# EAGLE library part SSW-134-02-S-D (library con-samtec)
THROUGH-HOLE .025" SQ POST SOCKET Source: Samtec SSW.pdf
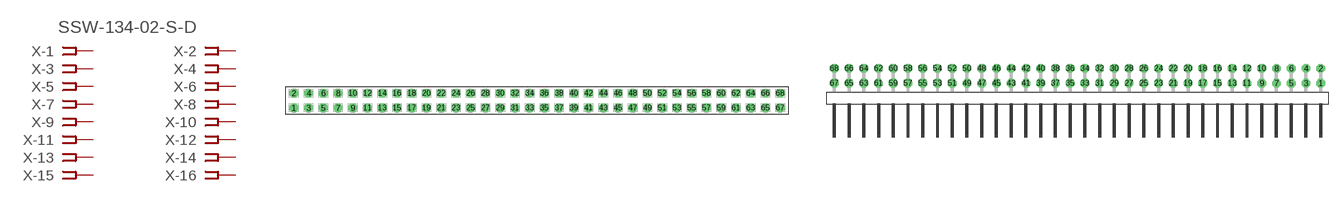
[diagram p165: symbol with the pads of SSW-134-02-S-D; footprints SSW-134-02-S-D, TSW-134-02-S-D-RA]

Designator prefix X; gates -1=FPINV -2=FPIN -3=FPIN -4=FPIN -5=FPIN -6=FPIN -7=FPIN -8=FPIN -9=FPIN -10=FPIN -11=FPIN -12=FPIN -13=FPIN -14=FPIN -15=FPIN -16=FPIN -17=FPIN -18=FPIN -19=FPIN -20=FPIN -21=FPIN -22=FPIN -23=FPIN -24=FPIN -25=FPIN -26=FPIN -27=FPIN -28=FPIN -29=FPIN -30=FPIN -31=FPIN -32=FPIN -33=FPIN -34=FPIN -35=FPIN -36=FPIN -37=FPIN -38=FPIN -39=FPIN -40=FPIN -41=FPIN -42=FPIN -43=FPIN -44=FPIN -45=FPIN -46=FPIN -47=FPIN -48=FPIN -49=FPIN -50=FPIN -51=FPIN -52=FPIN -53=FPIN -54=FPIN -55=FPIN -56=FPIN -57=FPIN -58=FPIN -59=FPIN -60=FPIN -61=FPIN -62=FPIN -63=FPIN -64=FPIN -65=FPIN -66=FPIN -67=FPIN -68=FPIN

## SSW-134-02-S-D (MPN: SSW-134-02-S-D; OC_FARNELL: unknown; OC_NEWARK: 11P9869)  [SSW-134-02-S-D]
1  -1:1  pas
2  -2:1  pas
3  -3:1  pas
4  -4:1  pas
5  -5:1  pas
6  -6:1  pas
7  -7:1  pas
8  -8:1  pas
9  -9:1  pas
10  -10:1  pas
11  -11:1  pas
12  -12:1  pas
13  -13:1  pas
14  -14:1  pas
15  -15:1  pas
16  -16:1  pas
17  -17:1  pas
18  -18:1  pas
19  -19:1  pas
20  -20:1  pas
21  -21:1  pas
22  -22:1  pas
23  -23:1  pas
24  -24:1  pas
25  -25:1  pas
26  -26:1  pas
27  -27:1  pas
28  -28:1  pas
29  -29:1  pas
30  -30:1  pas
31  -31:1  pas
32  -32:1  pas
33  -33:1  pas
34  -34:1  pas
35  -35:1  pas
36  -36:1  pas
37  -37:1  pas
38  -38:1  pas
39  -39:1  pas
40  -40:1  pas
41  -41:1  pas
42  -42:1  pas
43  -43:1  pas
44  -44:1  pas
45  -45:1  pas
46  -46:1  pas
47  -47:1  pas
48  -48:1  pas
49  -49:1  pas
50  -50:1  pas
51  -51:1  pas
52  -52:1  pas
53  -53:1  pas
54  -54:1  pas
55  -55:1  pas
56  -56:1  pas
57  -57:1  pas
58  -58:1  pas
59  -59:1  pas
60  -60:1  pas
61  -61:1  pas
62  -62:1  pas
63  -63:1  pas
64  -64:1  pas
65  -65:1  pas
66  -66:1  pas
67  -67:1  pas
68  -68:1  pas

## SSW-134-02-S-D-RA (MPN: SSW-134-02-S-D-RA; OC_FARNELL: unknown; OC_NEWARK: 11P9870)  [TSW-134-02-S-D-RA]
Pads as for SSW-134-02-S-D

## Footprint SSW-134-02-S-D (pad centres in mm)
THROUGH-HOLE .025" SQ POST SOCKET Source: Samtec SSW.pdf
drill 1 pad 1.5 octagon: 1 -41.91,-1.27; 2 -41.91,1.27; 3 -39.37,-1.27; 4 -39.37,1.27; 5 -36.83,-1.27; 6 -36.83,1.27; 7 -34.29,-1.27; 8 -34.29,1.27; 9 -31.75,-1.27; 10 -31.75,1.27; 11 -29.21,-1.27; 12 -29.21,1.27; 13 -26.67,-1.27; 14 -26.67,1.27; 15 -24.13,-1.27; 16 -24.13,1.27; 17 -21.59,-1.27; 18 -21.59,1.27; 19 -19.05,-1.27; 20 -19.05,1.27; 21 -16.51,-1.27; 22 -16.51,1.27; 23 -13.97,-1.27; 24 -13.97,1.27; 25 -11.43,-1.27; 26 -11.43,1.27; 27 -8.89,-1.27; 28 -8.89,1.27; 29 -6.35,-1.27; 30 -6.35,1.27; 31 -3.81,-1.27; 32 -3.81,1.27; 33 -1.27,-1.27; 34 -1.27,1.27; 35 1.27,-1.27; 36 1.27,1.27; 37 3.81,-1.27; 38 3.81,1.27; 39 6.35,-1.27; 40 6.35,1.27; 41 8.89,-1.27; 42 8.89,1.27; 43 11.43,-1.27; 44 11.43,1.27; 45 13.97,-1.27; 46 13.97,1.27; 47 16.51,-1.27; 48 16.51,1.27; 49 19.05,-1.27; 50 19.05,1.27; 51 21.59,-1.27; 52 21.59,1.27; 53 24.13,-1.27; 54 24.13,1.27; 55 26.67,-1.27; 56 26.67,1.27; 57 29.21,-1.27; 58 29.21,1.27; 59 31.75,-1.27; 60 31.75,1.27; 61 34.29,-1.27; 62 34.29,1.27; 63 36.83,-1.27; 64 36.83,1.27; 65 39.37,-1.27; 66 39.37,1.27; 67 41.91,-1.27; 68 41.91,1.27

## Footprint TSW-134-02-S-D-RA (pad centres in mm)
THROUGH-HOLE .025" SQ POST HEADER Source: Samtec TSW.pdf
drill 1 pad 1.5 octagon: 1 41.91,1.524; 2 41.91,4.064; 3 39.37,1.524; 4 39.37,4.064; 5 36.83,1.524; 6 36.83,4.064; 7 34.29,1.524; 8 34.29,4.064; 9 31.75,1.524; 10 31.75,4.064; 11 29.21,1.524; 12 29.21,4.064; 13 26.67,1.524; 14 26.67,4.064; 15 24.13,1.524; 16 24.13,4.064; 17 21.59,1.524; 18 21.59,4.064; 19 19.05,1.524; 20 19.05,4.064; 21 16.51,1.524; 22 16.51,4.064; 23 13.97,1.524; 24 13.97,4.064; 25 11.43,1.524; 26 11.43,4.064; 27 8.89,1.524; 28 8.89,4.064; 29 6.35,1.524; 30 6.35,4.064; 31 3.81,1.524; 32 3.81,4.064; 33 1.27,1.524; 34 1.27,4.064; 35 -1.27,1.524; 36 -1.27,4.064; 37 -3.81,1.524; 38 -3.81,4.064; 39 -6.35,1.524; 40 -6.35,4.064; 41 -8.89,1.524; 42 -8.89,4.064; 43 -11.43,1.524; 44 -11.43,4.064; 45 -13.97,1.524; 46 -13.97,4.064; 47 -16.51,1.524; 48 -16.51,4.064; 49 -19.05,1.524; 50 -19.05,4.064; 51 -21.59,1.524; 52 -21.59,4.064; 53 -24.13,1.524; 54 -24.13,4.064; 55 -26.67,1.524; 56 -26.67,4.064; 57 -29.21,1.524; 58 -29.21,4.064; 59 -31.75,1.524; 60 -31.75,4.064; 61 -34.29,1.524; 62 -34.29,4.064; 63 -36.83,1.524; 64 -36.83,4.064; 65 -39.37,1.524; 66 -39.37,4.064; 67 -41.91,1.524; 68 -41.91,4.064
